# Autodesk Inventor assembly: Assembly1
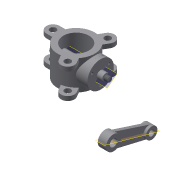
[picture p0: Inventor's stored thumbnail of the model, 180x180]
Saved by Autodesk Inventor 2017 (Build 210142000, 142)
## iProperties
Created: 2016-07
Part Number: Assembly1
Document SubType Name: Assembly
Designer: Sandeep
Author: Sandeep
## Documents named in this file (5)
- D:\KAVITA\Autodesk Inventor_2017_Project\Part's File\Inventor_2016_tut\c09_Inv_tut_2016\Assembly1.iam
- D:\KAVITA\Autodesk Inventor_2017_Project\Part's File\Inventor_2016_tut\c10_Inv_tut_2016\c10_tut01_inv\Butterfly Valve\Body.ipt
- D:\KAVITA\Autodesk Inventor_2017_Project\Part's File\Inventor_2016_tut\c09_Inv_tut_2016\c09_tut01_inv\Butterfly Valve\shaft1.ipt
- D:\KAVITA\Autodesk Inventor_2017_Project\Part's File\Inventor_2016_tut\c09_Inv_tut_2016\c09_tut01_inv\Butterfly Valve\Arm1.ipt
- D:\KAVITA\Autodesk Inventor_2017_Project\Part's File\Inventor_2016_tut\c09_Inv_tut_2016\c09_tut01_inv\Butterfly Valve\Retainer.ipt
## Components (4 placed, 4 different names)
1. Body:2 — Insert:1, Mate:1, Insert:2, Insert:3
2. shaft1:1 — Insert:1
3. Arm1:1
4. Retainer:1 — Mate:1, Insert:2, Insert:3
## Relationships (4: Insert 3, Mate 1)
- Insert:1: Body:2 ↔ shaft1:1
- Mate:1: Body:2 ↔ Retainer:1
- Insert:2: Body:2 ↔ Retainer:1
- Insert:3: Body:2 ↔ Retainer:1
